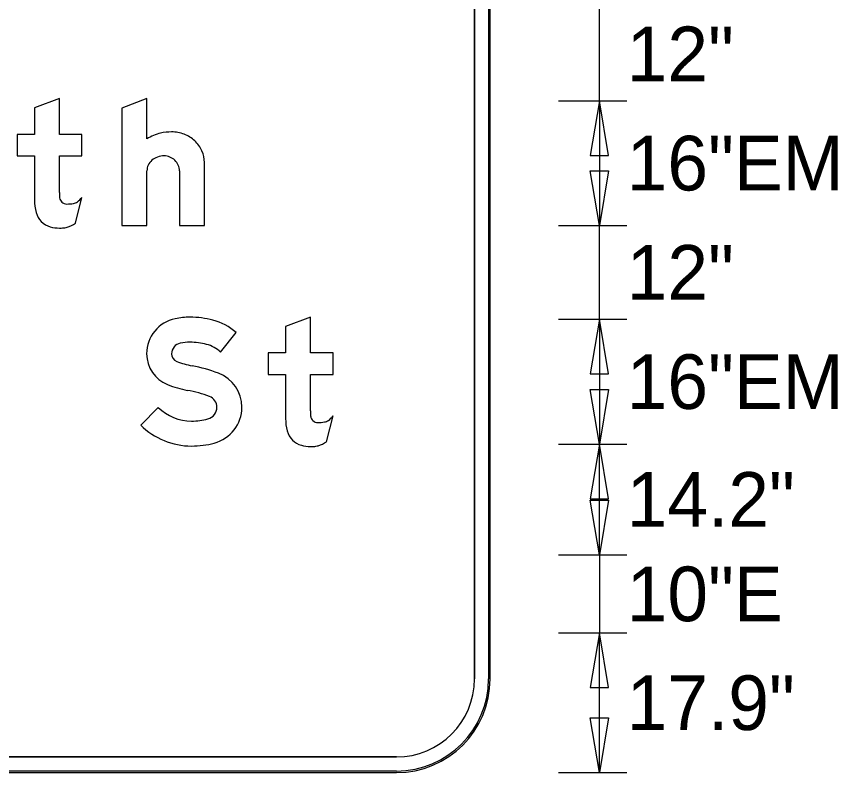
# Model space of a CAD drawing. Extents: x 2149961 to 2150220, y 145114 to 145240.
# Drawn here: x 2150205.58 to 2150214.34, y 145156.59 to 145164.66 of the extents above; entities that cross this region are included whole.
import ezdxf

# ---------------------------------------------------------------- set-up
doc = ezdxf.new("R2010")
doc.units = 0
for name, color, linetype in [('GSBWFILL', 7, 'Continuous'), ('GSCOLORFILL', 7, 'Continuous'), ('GSDIMS', 7, 'Continuous'), ('GSOUTLINE', 7, 'Continuous')]:
    doc.layers.add(name, color=color, linetype=linetype)

msp = doc.modelspace()

# ---------------------------------------------------------------- linework, layer by layer
at = {"layer": 'GSBWFILL'}
for p, q in [((2150210.4669, 145172.0853), (2150210.4669, 145157.5853)), ((2150210.6336, 145157.5853), (2150210.6336, 145172.0853)), ((2150206.2067, 145162.4518), (2150206.2768, 145162.7278)), ((2150208.8867, 145160.1185), (2150208.9569, 145160.3945)), ((2150209.6336, 145156.752), (2150196.1352, 145156.752)), ((2150196.1352, 145156.5853), (2150209.6336, 145156.5853))]:
    msp.add_line(p, q, dxfattribs=at)
for points in [[(2150206.0368, 145162.7804), (2150206.0368, 145163.1704), (2150206.2768, 145163.1704), (2150206.2768, 145163.4003), (2150206.0368, 145163.4003), (2150206.0368, 145163.7837), (2150205.7702, 145163.6825), (2150205.7702, 145163.4003), (2150205.5835, 145163.4003), (2150205.5835, 145163.1704), (2150205.7702, 145163.1704), (2150205.7702, 145162.6998)], [(2150206.9702, 145163.3522), (2150206.9702, 145163.7837), (2150206.7035, 145163.6808), (2150206.7035, 145162.427), (2150206.9702, 145162.427), (2150206.9702, 145163.0118)], [(2150207.3169, 145163.0118), (2150207.3169, 145162.427), (2150207.5835, 145162.427), (2150207.5835, 145163.0996)], [(2150208.7169, 145160.447), (2150208.7169, 145160.837), (2150208.9569, 145160.837), (2150208.9569, 145161.067), (2150208.7169, 145161.067), (2150208.7169, 145161.4504), (2150208.4502, 145161.3492), (2150208.4502, 145161.067), (2150208.2635, 145161.067), (2150208.2635, 145160.837), (2150208.4502, 145160.837), (2150208.4502, 145160.3664)], [(2150207.7569, 145161.0751), (2150207.9218, 145161.2855)], [(2150207.0913, 145160.4855), (2150206.9035, 145160.2961)]]:
    msp.add_lwpolyline(points, dxfattribs=at)
for centre, radius, start, end in [((2150207.2281, 145162.9472), 0.4802, 103.46954, 122.49426), ((2150207.2327, 145162.8936), 0.5334, 90, 102.60428), ((2150207.2327, 145163.0516), 0.3754, 68.86358, 90), ((2150207.2417, 145163.075), 0.3503, 46.97501, 68.86358), ((2150207.2557, 145163.09), 0.3299, 23.93172, 46.97501), ((2150207.1531, 145162.961), 0.2099, 90, 109.80736), ((2150207.1531, 145163.0024), 0.1684, 68.08083, 90), ((2150207.2774, 145163.0996), 0.3062, 0, 23.93172), ((2150207.1304, 145163.0016), 0.1625, 131.00764, 154.52827), ((2150207.1442, 145162.9858), 0.1835, 109.80736, 131.00764), ((2150207.155, 145163.007), 0.1635, 45.8298, 68.08083), ((2150207.1578, 145163.0099), 0.1594, 23.09284, 45.82979), ((2150207.1091, 145163.0118), 0.1389, 154.52827, 180), ((2150207.1622, 145163.0118), 0.1546, 0, 23.09285), ((2150209.6336, 145157.5853), 1, 270, 0), ((2150209.6336, 145157.5853), 0.8333, 270, 0)]:
    msp.add_arc(centre, radius, start, end, dxfattribs=at)
for centre, major_axis, ratio, start_param, end_param in [((2150207.7061, 145162.7804), (0, 1.6693), 0.99999, 1.570796, 1.606005), ((2150206.1013, 145162.8587), (0, 0.2189), 0.99999, 3.756278, 4.071638), ((2150206.2876, 145162.6998), (0, 0.5174), 0.99999, 1.570796, 1.830698), ((2150206.1134, 145162.7346), (0, 0.0767), 0.99999, 1.74085, 2.407828), ((2150206.1159, 145162.7372), (0, 0.0803), 0.99999, 2.407828, 3.141593), ((2150206.1159, 145163.0781), (0, 0.4211), 0.99999, 3.141593, 3.310762), ((2150206.1699, 145162.7616), (0, 0.1), 0.99999, 3.310762, 3.756278), ((2150205.9969, 145162.6225), (0, 0.2167), 0.99999, 1.830698, 2.869526), ((2150206.0368, 145162.7655), (0, 0.3651), 0.99999, 2.869526, 3.141593), ((2150206.0368, 145162.9262), (0, 0.5258), 0.99999, 3.141593, 3.205734), ((2150206.0567, 145162.6177), (0, 0.2167), 0.99999, 3.205734, 3.427755), ((2150206.0283, 145162.7141), (0, 0.3172), 0.99999, 3.427755, 3.738844), ((2150207.3489, 145161.0578), (0, 0.382), 0.999996, 0.202758, 1.570796), ((2150207.4302, 145160.6626), (0, 0.7855), 0.999996, 0, 0.202758), ((2150207.4302, 145160.4848), (0, 0.9632), 0.999996, 6.026234, 6.283185), ((2150207.5195, 145160.825), (0, 0.6115), 0.999996, 5.565152, 6.026234), ((2150207.3489, 145161.0578), (0, 0.1153), 0.999996, 0.202758, 1.570796), ((2150207.4302, 145160.6626), (0, 0.5188), 0.999996, 0, 0.202758), ((2150207.4302, 145160.4848), (0, 0.6965), 0.999996, 6.026234, 6.283185), ((2150207.5195, 145160.825), (0, 0.3448), 0.999996, 5.523837, 6.026234), ((2150207.3208, 145161.0578), (0, 0.3538), 0.999996, 1.570796, 2.761249), ((2150207.3208, 145161.0578), (0, 0.0872), 0.999996, 1.570796, 2.761249), ((2150207.6114, 145161.7846), (0, 0.8699), 0.999996, 2.761249, 2.95744), ((2150207.1548, 145159.3336), (0, 1.6233), 0.999996, 5.918637, 6.099033), ((2150207.5951, 145160.4872), (0, 0.3885), 0.999996, 4.712389, 5.918637), ((2150207.6114, 145161.7846), (0, 1.1366), 0.999996, 2.761249, 2.95744), ((2150207.1548, 145159.3336), (0, 1.3566), 0.999996, 5.918637, 6.099033), ((2150207.5951, 145160.4872), (0, 0.1218), 0.999996, 4.712389, 5.918637), ((2150207.4464, 145160.8438), (0, 0.5044), 0.999996, 2.360607, 3.141593), ((2150207.5874, 145160.4872), (0, 0.1295), 0.999996, 3.401517, 4.712389), ((2150207.5874, 145160.4872), (0, 0.3961), 0.999996, 3.401517, 4.712389), ((2150210.3861, 145160.447), (0, 1.6693), 0.999994, 1.570796, 1.606005), ((2150207.4464, 145161.0176), (0, 0.6782), 0.999996, 3.141593, 3.401517), ((2150208.9676, 145160.3664), (0, 0.5174), 0.999994, 1.570796, 1.830698), ((2150208.7935, 145160.4012), (0, 0.0767), 0.999994, 1.74085, 2.407828), ((2150208.7814, 145160.5254), (0, 0.2189), 0.999994, 3.756278, 4.071638), ((2150207.4464, 145160.8438), (0, 0.7711), 0.999996, 2.360607, 3.141593), ((2150208.7959, 145160.4039), (0, 0.0803), 0.999994, 2.407828, 3.141593), ((2150208.7959, 145160.7448), (0, 0.4211), 0.999994, 3.141593, 3.310762), ((2150208.8499, 145160.4282), (0, 0.1), 0.999994, 3.310762, 3.756278), ((2150208.677, 145160.2891), (0, 0.2167), 0.999994, 1.830698, 2.869526), ((2150207.4464, 145161.0176), (0, 0.9449), 0.999996, 3.141593, 3.401517), ((2150208.7083, 145160.3808), (0, 0.3172), 0.999994, 3.427755, 3.738844), ((2150208.7169, 145160.4321), (0, 0.3651), 0.999994, 2.869526, 3.141593), ((2150208.7169, 145160.5929), (0, 0.5258), 0.999994, 3.141593, 3.205734), ((2150208.7367, 145160.2843), (0, 0.2167), 0.999994, 3.205734, 3.427755)]:
    msp.add_ellipse(centre, major_axis=major_axis, ratio=ratio, start_param=start_param, end_param=end_param, dxfattribs=at)
at = {"layer": 'GSCOLORFILL'}
for p, q in [((2150210.4669, 145172.0853), (2150210.4669, 145157.5853)), ((2150210.6169, 145172.0853), (2150210.6169, 145157.5853)), ((2150210.6336, 145157.5853), (2150210.6336, 145172.0853)), ((2150210.6336, 145157.5853), (2150210.6336, 145172.0853)), ((2150210.6336, 145157.5853), (2150210.6336, 145172.0853)), ((2150206.2067, 145162.4518), (2150206.2768, 145162.7278)), ((2150208.8867, 145160.1185), (2150208.9569, 145160.3945)), ((2150209.6336, 145156.752), (2150196.1352, 145156.752)), ((2150209.6336, 145156.602), (2150196.1337, 145156.602)), ((2150196.1336, 145156.5853), (2150209.6336, 145156.5853)), ((2150196.1337, 145156.5853), (2150209.6336, 145156.5853)), ((2150196.1352, 145156.5853), (2150209.6336, 145156.5853))]:
    msp.add_line(p, q, dxfattribs=at)
for points in [[(2150206.0368, 145162.7804), (2150206.0368, 145163.1704), (2150206.2768, 145163.1704), (2150206.2768, 145163.4003), (2150206.0368, 145163.4003), (2150206.0368, 145163.7837), (2150205.7702, 145163.6825), (2150205.7702, 145163.4003), (2150205.5835, 145163.4003), (2150205.5835, 145163.1704), (2150205.7702, 145163.1704), (2150205.7702, 145162.6998)], [(2150206.9702, 145163.3522), (2150206.9702, 145163.7837), (2150206.7035, 145163.6808), (2150206.7035, 145162.427), (2150206.9702, 145162.427), (2150206.9702, 145163.0118)], [(2150207.3169, 145163.0118), (2150207.3169, 145162.427), (2150207.5835, 145162.427), (2150207.5835, 145163.0996)], [(2150208.7169, 145160.447), (2150208.7169, 145160.837), (2150208.9569, 145160.837), (2150208.9569, 145161.067), (2150208.7169, 145161.067), (2150208.7169, 145161.4504), (2150208.4502, 145161.3492), (2150208.4502, 145161.067), (2150208.2635, 145161.067), (2150208.2635, 145160.837), (2150208.4502, 145160.837), (2150208.4502, 145160.3664)], [(2150207.7569, 145161.0751), (2150207.9218, 145161.2855)], [(2150207.0913, 145160.4855), (2150206.9035, 145160.2961)]]:
    msp.add_lwpolyline(points, dxfattribs=at)
for centre, radius, start, end in [((2150207.2281, 145162.9472), 0.4802, 103.46954, 122.49426), ((2150207.2327, 145162.8936), 0.5334, 90, 102.60428), ((2150207.2327, 145163.0516), 0.3754, 68.86358, 90), ((2150207.2417, 145163.075), 0.3503, 46.97501, 68.86358), ((2150207.2557, 145163.09), 0.3299, 23.93172, 46.97501), ((2150207.1531, 145162.961), 0.2099, 90, 109.80736), ((2150207.1531, 145163.0024), 0.1684, 68.08083, 90), ((2150207.2774, 145163.0996), 0.3062, 0, 23.93172), ((2150207.1304, 145163.0016), 0.1625, 131.00764, 154.52827), ((2150207.1442, 145162.9858), 0.1835, 109.80736, 131.00764), ((2150207.155, 145163.007), 0.1635, 45.8298, 68.08083), ((2150207.1578, 145163.0099), 0.1594, 23.09284, 45.82979), ((2150207.1091, 145163.0118), 0.1389, 154.52827, 180), ((2150207.1622, 145163.0118), 0.1546, 0, 23.09285), ((2150209.6336, 145157.5853), 1, 270, 0), ((2150209.6336, 145157.5853), 1, 270, 0), ((2150209.6336, 145157.5853), 0.8333, 270, 0), ((2150209.6336, 145157.5853), 1, 270, 0), ((2150209.6336, 145157.5853), 0.9833, 270, 0)]:
    msp.add_arc(centre, radius, start, end, dxfattribs=at)
for centre, major_axis, ratio, start_param, end_param in [((2150207.7061, 145162.7804), (0, 1.6693), 0.99999, 1.570796, 1.606005), ((2150206.1013, 145162.8587), (0, 0.2189), 0.99999, 3.756278, 4.071638), ((2150206.2876, 145162.6998), (0, 0.5174), 0.99999, 1.570796, 1.830698), ((2150206.1134, 145162.7346), (0, 0.0767), 0.99999, 1.74085, 2.407828), ((2150206.1159, 145162.7372), (0, 0.0803), 0.99999, 2.407828, 3.141593), ((2150206.1159, 145163.0781), (0, 0.4211), 0.99999, 3.141593, 3.310762), ((2150206.1699, 145162.7616), (0, 0.1), 0.99999, 3.310762, 3.756278), ((2150205.9969, 145162.6225), (0, 0.2167), 0.99999, 1.830698, 2.869526), ((2150206.0368, 145162.7655), (0, 0.3651), 0.99999, 2.869526, 3.141593), ((2150206.0368, 145162.9262), (0, 0.5258), 0.99999, 3.141593, 3.205734), ((2150206.0567, 145162.6177), (0, 0.2167), 0.99999, 3.205734, 3.427755), ((2150206.0283, 145162.7141), (0, 0.3172), 0.99999, 3.427755, 3.738844), ((2150207.3489, 145161.0578), (0, 0.382), 0.999996, 0.202758, 1.570796), ((2150207.4302, 145160.6626), (0, 0.7855), 0.999996, 0, 0.202758), ((2150207.4302, 145160.4848), (0, 0.9632), 0.999996, 6.026234, 6.283185), ((2150207.5195, 145160.825), (0, 0.6115), 0.999996, 5.565152, 6.026234), ((2150207.3489, 145161.0578), (0, 0.1153), 0.999996, 0.202758, 1.570796), ((2150207.4302, 145160.6626), (0, 0.5188), 0.999996, 0, 0.202758), ((2150207.4302, 145160.4848), (0, 0.6965), 0.999996, 6.026234, 6.283185), ((2150207.5195, 145160.825), (0, 0.3448), 0.999996, 5.523837, 6.026234), ((2150207.3208, 145161.0578), (0, 0.3538), 0.999996, 1.570796, 2.761249), ((2150207.3208, 145161.0578), (0, 0.0872), 0.999996, 1.570796, 2.761249), ((2150207.6114, 145161.7846), (0, 0.8699), 0.999996, 2.761249, 2.95744), ((2150207.1548, 145159.3336), (0, 1.6233), 0.999996, 5.918637, 6.099033), ((2150207.5951, 145160.4872), (0, 0.3885), 0.999996, 4.712389, 5.918637), ((2150207.6114, 145161.7846), (0, 1.1366), 0.999996, 2.761249, 2.95744), ((2150207.1548, 145159.3336), (0, 1.3566), 0.999996, 5.918637, 6.099033), ((2150207.5951, 145160.4872), (0, 0.1218), 0.999996, 4.712389, 5.918637), ((2150207.4464, 145160.8438), (0, 0.5044), 0.999996, 2.360607, 3.141593), ((2150207.5874, 145160.4872), (0, 0.1295), 0.999996, 3.401517, 4.712389), ((2150207.5874, 145160.4872), (0, 0.3961), 0.999996, 3.401517, 4.712389), ((2150210.3861, 145160.447), (0, 1.6693), 0.999994, 1.570796, 1.606005), ((2150207.4464, 145161.0176), (0, 0.6782), 0.999996, 3.141593, 3.401517), ((2150208.9676, 145160.3664), (0, 0.5174), 0.999994, 1.570796, 1.830698), ((2150208.7935, 145160.4012), (0, 0.0767), 0.999994, 1.74085, 2.407828), ((2150208.7814, 145160.5254), (0, 0.2189), 0.999994, 3.756278, 4.071638), ((2150207.4464, 145160.8438), (0, 0.7711), 0.999996, 2.360607, 3.141593), ((2150208.7959, 145160.4039), (0, 0.0803), 0.999994, 2.407828, 3.141593), ((2150208.7959, 145160.7448), (0, 0.4211), 0.999994, 3.141593, 3.310762), ((2150208.8499, 145160.4282), (0, 0.1), 0.999994, 3.310762, 3.756278), ((2150208.677, 145160.2891), (0, 0.2167), 0.999994, 1.830698, 2.869526), ((2150207.4464, 145161.0176), (0, 0.9449), 0.999996, 3.141593, 3.401517), ((2150208.7083, 145160.3808), (0, 0.3172), 0.999994, 3.427755, 3.738844), ((2150208.7169, 145160.4321), (0, 0.3651), 0.999994, 2.869526, 3.141593), ((2150208.7169, 145160.5929), (0, 0.5258), 0.999994, 3.141593, 3.205734), ((2150208.7367, 145160.2843), (0, 0.2167), 0.999994, 3.205734, 3.427755)]:
    msp.add_ellipse(centre, major_axis=major_axis, ratio=ratio, start_param=start_param, end_param=end_param, dxfattribs=at)
at = {"layer": 'GSDIMS'}
for p, q in [((2150211.8003, 145163.7603), (2150211.8003, 145164.7603)), ((2150211.3628, 145163.7603), (2150212.0919, 145163.7603)), ((2150211.3628, 145163.7603), (2150212.0919, 145163.7603)), ((2150211.8003, 145163.7603), (2150211.8003, 145162.427)), ((2150211.3628, 145162.427), (2150212.0919, 145162.427)), ((2150211.3628, 145162.427), (2150212.0919, 145162.427)), ((2150211.8003, 145161.427), (2150211.8003, 145162.427)), ((2150211.3628, 145161.427), (2150212.0919, 145161.427)), ((2150211.3628, 145161.427), (2150212.0919, 145161.427)), ((2150211.8003, 145161.427), (2150211.8003, 145160.0937)), ((2150211.3628, 145160.0937), (2150212.0919, 145160.0937)), ((2150211.3628, 145160.0937), (2150212.0919, 145160.0937)), ((2150211.8003, 145158.9104), (2150211.8003, 145160.0937)), ((2150211.3628, 145158.9104), (2150212.0919, 145158.9104)), ((2150211.3628, 145158.9104), (2150212.0919, 145158.9104)), ((2150211.8003, 145158.9104), (2150211.8003, 145158.077)), ((2150211.3628, 145158.077), (2150212.0919, 145158.077)), ((2150211.3628, 145158.077), (2150212.0919, 145158.077)), ((2150211.8003, 145156.5853), (2150211.8003, 145158.077)), ((2150211.3628, 145156.5853), (2150212.0919, 145156.5853)), ((2150211.3628, 145156.5853), (2150211.3628, 145156.5853))]:
    msp.add_line(p, q, dxfattribs=at)
for points in [[(2150211.8003, 145163.7603), (2150211.7031, 145163.177), (2150211.8975, 145163.177)], [(2150211.8003, 145162.427), (2150211.7031, 145163.0104), (2150211.8975, 145163.0104)], [(2150211.8003, 145161.427), (2150211.7031, 145160.8437), (2150211.8975, 145160.8437)], [(2150211.8003, 145160.0937), (2150211.7031, 145160.677), (2150211.8975, 145160.677)], [(2150211.8003, 145160.0937), (2150211.7031, 145159.5104), (2150211.8975, 145159.5104)], [(2150211.8003, 145158.9104), (2150211.7031, 145159.4937), (2150211.8975, 145159.4937)], [(2150211.8003, 145158.077), (2150211.7031, 145157.4937), (2150211.8975, 145157.4937)], [(2150211.8003, 145156.5853), (2150211.7031, 145157.1687), (2150211.8975, 145157.1687)]]:
    msp.add_lwpolyline(points, close=True, dxfattribs=at)
at = {"layer": 'GSOUTLINE'}
for p, q in [((2150210.4669, 145157.5853), (2150210.4669, 145172.0853)), ((2150210.6336, 145157.5853), (2150210.6336, 145172.0853)), ((2150206.2067, 145162.4518), (2150206.2768, 145162.7278)), ((2150208.8867, 145160.1185), (2150208.9569, 145160.3945)), ((2150196.1336, 145156.752), (2150209.6336, 145156.752)), ((2150196.1336, 145156.5853), (2150209.6336, 145156.5853))]:
    msp.add_line(p, q, dxfattribs=at)
for points in [[(2150206.0368, 145162.7804), (2150206.0368, 145163.1704), (2150206.2768, 145163.1704), (2150206.2768, 145163.4003), (2150206.0368, 145163.4003), (2150206.0368, 145163.7837), (2150205.7702, 145163.6825), (2150205.7702, 145163.4003), (2150205.5835, 145163.4003), (2150205.5835, 145163.1704), (2150205.7702, 145163.1704), (2150205.7702, 145162.6998)], [(2150206.9702, 145163.3522), (2150206.9702, 145163.7837), (2150206.7035, 145163.6808), (2150206.7035, 145162.427), (2150206.9702, 145162.427), (2150206.9702, 145163.0118)], [(2150207.3169, 145163.0118), (2150207.3169, 145162.427), (2150207.5835, 145162.427), (2150207.5835, 145163.0996)], [(2150208.7169, 145160.447), (2150208.7169, 145160.837), (2150208.9569, 145160.837), (2150208.9569, 145161.067), (2150208.7169, 145161.067), (2150208.7169, 145161.4504), (2150208.4502, 145161.3492), (2150208.4502, 145161.067), (2150208.2635, 145161.067), (2150208.2635, 145160.837), (2150208.4502, 145160.837), (2150208.4502, 145160.3664)], [(2150207.7569, 145161.0751), (2150207.9218, 145161.2855)], [(2150207.0913, 145160.4855), (2150206.9035, 145160.2961)]]:
    msp.add_lwpolyline(points, dxfattribs=at)
for centre, radius, start, end in [((2150207.2281, 145162.9472), 0.4802, 103.46954, 122.49426), ((2150207.2327, 145162.8936), 0.5334, 90, 102.60428), ((2150207.2327, 145163.0516), 0.3754, 68.86358, 90), ((2150207.2417, 145163.075), 0.3503, 46.97501, 68.86358), ((2150207.2557, 145163.09), 0.3299, 23.93172, 46.97501), ((2150207.1531, 145162.961), 0.2099, 90, 109.80736), ((2150207.1531, 145163.0024), 0.1684, 68.08083, 90), ((2150207.2774, 145163.0996), 0.3062, 0, 23.93172), ((2150207.1304, 145163.0016), 0.1625, 131.00764, 154.52827), ((2150207.1442, 145162.9858), 0.1835, 109.80736, 131.00764), ((2150207.155, 145163.007), 0.1635, 45.8298, 68.08083), ((2150207.1578, 145163.0099), 0.1594, 23.09284, 45.82979), ((2150207.1091, 145163.0118), 0.1389, 154.52827, 180), ((2150207.1622, 145163.0118), 0.1546, 0, 23.09285), ((2150209.6336, 145157.5853), 1, 270, 0), ((2150209.6336, 145157.5853), 0.8333, 270, 0)]:
    msp.add_arc(centre, radius, start, end, dxfattribs=at)
for centre, major_axis, ratio, start_param, end_param in [((2150207.7061, 145162.7804), (0, 1.6693), 0.99999, 1.570796, 1.606005), ((2150206.1013, 145162.8587), (0, 0.2189), 0.99999, 3.756278, 4.071638), ((2150206.2876, 145162.6998), (0, 0.5174), 0.99999, 1.570796, 1.830698), ((2150206.1134, 145162.7346), (0, 0.0767), 0.99999, 1.74085, 2.407828), ((2150206.1159, 145162.7372), (0, 0.0803), 0.99999, 2.407828, 3.141593), ((2150206.1159, 145163.0781), (0, 0.4211), 0.99999, 3.141593, 3.310762), ((2150206.1699, 145162.7616), (0, 0.1), 0.99999, 3.310762, 3.756278), ((2150205.9969, 145162.6225), (0, 0.2167), 0.99999, 1.830698, 2.869526), ((2150206.0368, 145162.7655), (0, 0.3651), 0.99999, 2.869526, 3.141593), ((2150206.0368, 145162.9262), (0, 0.5258), 0.99999, 3.141593, 3.205734), ((2150206.0567, 145162.6177), (0, 0.2167), 0.99999, 3.205734, 3.427755), ((2150206.0283, 145162.7141), (0, 0.3172), 0.99999, 3.427755, 3.738844), ((2150207.3489, 145161.0578), (0, 0.382), 0.999996, 0.202758, 1.570796), ((2150207.4302, 145160.6626), (0, 0.7855), 0.999996, 0, 0.202758), ((2150207.4302, 145160.4848), (0, 0.9632), 0.999996, 6.026234, 6.283185), ((2150207.5195, 145160.825), (0, 0.6115), 0.999996, 5.565152, 6.026234), ((2150207.3489, 145161.0578), (0, 0.1153), 0.999996, 0.202758, 1.570796), ((2150207.4302, 145160.6626), (0, 0.5188), 0.999996, 0, 0.202758), ((2150207.4302, 145160.4848), (0, 0.6965), 0.999996, 6.026234, 6.283185), ((2150207.5195, 145160.825), (0, 0.3448), 0.999996, 5.523837, 6.026234), ((2150207.3208, 145161.0578), (0, 0.3538), 0.999996, 1.570796, 2.761249), ((2150207.3208, 145161.0578), (0, 0.0872), 0.999996, 1.570796, 2.761249), ((2150207.6114, 145161.7846), (0, 0.8699), 0.999996, 2.761249, 2.95744), ((2150207.1548, 145159.3336), (0, 1.6233), 0.999996, 5.918637, 6.099033), ((2150207.5951, 145160.4872), (0, 0.3885), 0.999996, 4.712389, 5.918637), ((2150207.6114, 145161.7846), (0, 1.1366), 0.999996, 2.761249, 2.95744), ((2150207.1548, 145159.3336), (0, 1.3566), 0.999996, 5.918637, 6.099033), ((2150207.5951, 145160.4872), (0, 0.1218), 0.999996, 4.712389, 5.918637), ((2150207.4464, 145160.8438), (0, 0.5044), 0.999996, 2.360607, 3.141593), ((2150207.5874, 145160.4872), (0, 0.1295), 0.999996, 3.401517, 4.712389), ((2150207.5874, 145160.4872), (0, 0.3961), 0.999996, 3.401517, 4.712389), ((2150210.3861, 145160.447), (0, 1.6693), 0.999994, 1.570796, 1.606005), ((2150207.4464, 145161.0176), (0, 0.6782), 0.999996, 3.141593, 3.401517), ((2150208.9676, 145160.3664), (0, 0.5174), 0.999994, 1.570796, 1.830698), ((2150208.7935, 145160.4012), (0, 0.0767), 0.999994, 1.74085, 2.407828), ((2150208.7814, 145160.5254), (0, 0.2189), 0.999994, 3.756278, 4.071638), ((2150207.4464, 145160.8438), (0, 0.7711), 0.999996, 2.360607, 3.141593), ((2150208.7959, 145160.4039), (0, 0.0803), 0.999994, 2.407828, 3.141593), ((2150208.7959, 145160.7448), (0, 0.4211), 0.999994, 3.141593, 3.310762), ((2150208.8499, 145160.4282), (0, 0.1), 0.999994, 3.310762, 3.756278), ((2150208.677, 145160.2891), (0, 0.2167), 0.999994, 1.830698, 2.869526), ((2150207.4464, 145161.0176), (0, 0.9449), 0.999996, 3.141593, 3.401517), ((2150208.7083, 145160.3808), (0, 0.3172), 0.999994, 3.427755, 3.738844), ((2150208.7169, 145160.4321), (0, 0.3651), 0.999994, 2.869526, 3.141593), ((2150208.7169, 145160.5929), (0, 0.5258), 0.999994, 3.141593, 3.205734), ((2150208.7367, 145160.2843), (0, 0.2167), 0.999994, 3.205734, 3.427755)]:
    msp.add_ellipse(centre, major_axis=major_axis, ratio=ratio, start_param=start_param, end_param=end_param, dxfattribs=at)

# ---------------------------------------------------------------- texts
at = {"layer": 'GSDIMS'}
for s, p in [('12"', (2150212.092, 145163.9687)), ('16"EM', (2150212.092, 145162.802)), ('12"', (2150212.092, 145161.6354)), ('16"EM', (2150212.092, 145160.4687)), ('14.2"', (2150212.092, 145159.2104)), ('10"E', (2150212.092, 145158.202)), ('17.9"', (2150212.092, 145157.0395))]:
    msp.add_text(s, height=0.58333, dxfattribs=at).set_placement(p)

doc.saveas('drawing.dxf')
